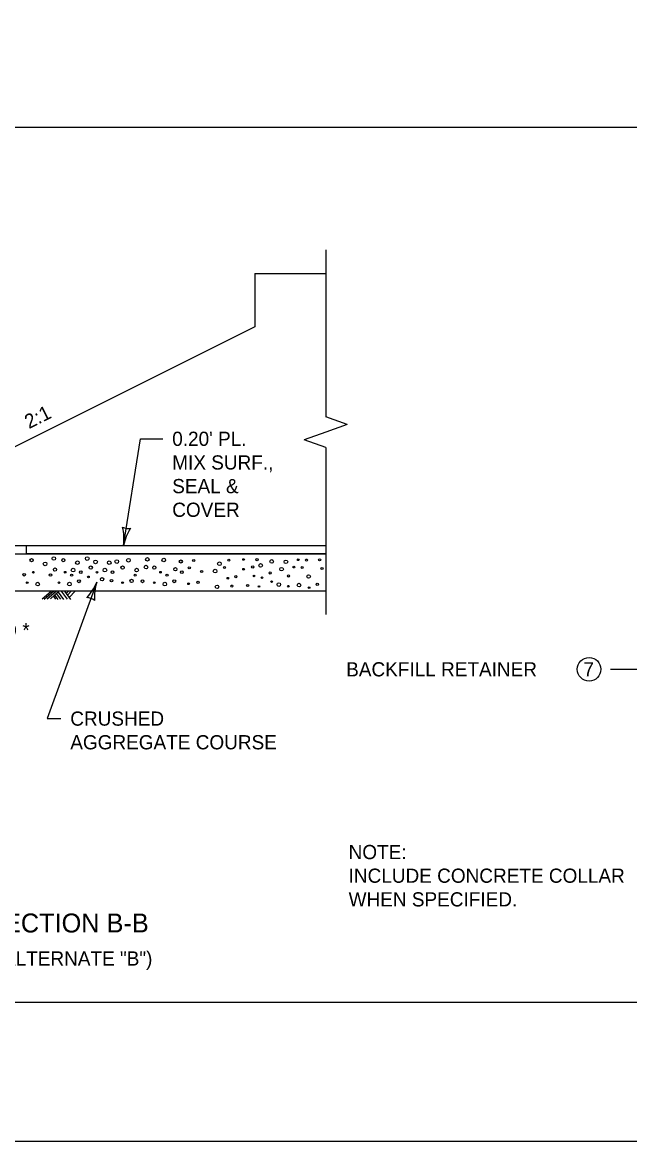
# Model space of a CAD drawing. Extents: x 49991.4 to 50021, y 49987.6 to 50011.4.
# Drawn here: x 50009.276 to 50011.844, y 49987.799 to 49992.53 of the extents above; entities that cross this region are included whole.
import ezdxf

# ---------------------------------------------------------------- set-up
doc = ezdxf.new("R2010")
doc.units = 0
for name, color, linetype in [('Level 1', 7, 'Continuous'), ('Level 2', 7, 'Continuous'), ('Level 3', 7, 'Continuous'), ('Level 6', 7, 'Continuous')]:
    doc.layers.add(name, color=color, linetype=linetype)

msp = doc.modelspace()

# ---------------------------------------------------------------- linework, layer by layer
at = {"layer": 'Level 1'}
for p, q in [((50010.2587, 49991.4692), (50010.2587, 49991.2434)), ((50010.2587, 49991.4692), (50010.5584, 49991.4692)), ((50010.2587, 49991.2434), (50008.4789, 49990.3535)), ((50008.5959, 49990.3188), (50010.5584, 49990.3188)), ((50009.2934, 49990.2833), (50009.2934, 49990.3188)), ((50009.2934, 49990.3188), (50010.5584, 49990.3188)), ((50010.5584, 49990.3188), (50010.5584, 49990.2833)), ((50008.5959, 49990.2833), (50010.5584, 49990.2833)), ((50010.5584, 49990.2833), (50009.2934, 49990.2833)), ((50008.4789, 49990.1273), (50010.5584, 49990.1273)), ((50009.3968, 49990.1248), (50009.3598, 49990.0925)), ((50009.4066, 49990.1248), (50009.3677, 49990.0908)), ((50009.4189, 49990.1249), (50009.3808, 49990.0918)), ((50009.4305, 49990.1252), (50009.3941, 49990.0934)), ((50009.4125, 49990.108), (50009.425, 49990.0908)), ((50009.4191, 49990.1152), (50009.4365, 49990.0914)), ((50009.4274, 49990.1218), (50009.4499, 49990.0909)), ((50009.4403, 49990.1255), (50009.4649, 49990.0919)), ((50009.4531, 49990.1257), (50009.4791, 49990.0901)), ((50009.4601, 49990.1143), (50009.4709, 49990.1257)), ((50009.4654, 49990.1074), (50009.4838, 49990.1268)), ((50009.4736, 49990.0982), (50009.499, 49990.1252)), ((50009.4072, 49990.1041), (50009.4156, 49990.0925))]:
    msp.add_line(p, q, dxfattribs=at)
for points in [[(49999.3835, 49998.9992), (50016.7501, 49998.9992), (50016.7501, 49987.7988), (49999.3835, 49987.7988)], [(49999.5517, 49992.0867), (50014.5753, 49992.0867), (50014.5753, 49988.387), (49999.5517, 49988.387)]]:
    msp.add_lwpolyline(points, close=True, dxfattribs=at)
for centre, radius in [((50009.3144, 49990.2567), 0.00684), ((50009.3719, 49990.2411), 0.00765), ((50009.4086, 49990.2637), 0.00765), ((50009.4488, 49990.2567), 0.00684), ((50009.5085, 49990.246), 0.00766), ((50009.5499, 49990.2636), 0.00765), ((50009.5852, 49990.2495), 0.00765), ((50009.643, 49990.246), 0.00766), ((50009.6747, 49990.2507), 0.00765), ((50009.7241, 49990.2564), 0.00765), ((50009.8042, 49990.2601), 0.00766), ((50009.8735, 49990.2572), 0.00765), ((50009.9458, 49990.251), 0.00684), ((50010.0001, 49990.2554), 0.0046), ((50010.1091, 49990.2416), 0.00766), ((50010.1487, 49990.2566), 0.0046), ((50010.211, 49990.2595), 0.00341), ((50010.2682, 49990.2591), 0.0046), ((50010.33, 49990.2514), 0.00766), ((50010.3901, 49990.2497), 0.00766), ((50010.4423, 49990.2584), 0.00341), ((50010.4775, 49990.257), 0.0046), ((50010.5327, 49990.2581), 0.0046), ((50009.322, 49990.2058), 0.00341), ((50009.4135, 49990.2171), 0.00684), ((50009.4565, 49990.2058), 0.00341), ((50009.4902, 49990.2149), 0.00766), ((50009.5223, 49990.2058), 0.00552), ((50009.5649, 49990.2256), 0.00684), ((50009.5909, 49990.2058), 0.00341), ((50009.6246, 49990.2149), 0.00766), ((50009.6568, 49990.2058), 0.00552), ((50009.6993, 49990.2256), 0.00684), ((50009.759, 49990.2149), 0.00766), ((50009.7987, 49990.2275), 0.00765), ((50009.8337, 49990.2256), 0.00684), ((50009.8598, 49990.2058), 0.00341), ((50009.9227, 49990.2185), 0.00684), ((50009.9499, 49990.2058), 0.00552), ((50009.9817, 49990.2243), 0.0046), ((50010.0338, 49990.2087), 0.0046), ((50010.0908, 49990.2105), 0.00766), ((50010.1303, 49990.2255), 0.0046), ((50010.211, 49990.2185), 0.00341), ((50010.2498, 49990.228), 0.0046), ((50010.2834, 49990.2345), 0.00766), ((50010.3237, 49990.2028), 0.0046), ((50010.3718, 49990.2186), 0.00766), ((50010.4239, 49990.2273), 0.00341), ((50010.4591, 49990.2259), 0.0046), ((50010.5431, 49990.2215), 0.0046), ((50009.2835, 49990.1952), 0.00552), ((50009.296, 49990.1615), 0.00341), ((50009.3404, 49990.1554), 0.00766), ((50009.3947, 49990.194), 0.00552), ((50009.4304, 49990.1615), 0.00341), ((50009.4748, 49990.1554), 0.00766), ((50009.484, 49990.1935), 0.0046), ((50009.5147, 49990.1676), 0.00613), ((50009.555, 49990.1861), 0.00341), ((50009.6129, 49990.1762), 0.00684), ((50009.6522, 49990.17), 0.00552), ((50009.6993, 49990.1615), 0.00341), ((50009.7374, 49990.1691), 0.00684), ((50009.7529, 49990.1935), 0.0046), ((50009.7835, 49990.1676), 0.00613), ((50009.8337, 49990.1615), 0.00341), ((50009.8782, 49990.1554), 0.00766), ((50009.8873, 49990.1935), 0.0046), ((50009.918, 49990.1676), 0.00613), ((50009.9785, 49990.1569), 0.00341), ((50010.0186, 49990.1627), 0.0046), ((50010.1445, 49990.1805), 0.00341), ((50010.1782, 49990.1871), 0.0046), ((50010.2282, 49990.1496), 0.0046), ((50010.2553, 49990.1898), 0.00341), ((50010.2893, 49990.1826), 0.00341), ((50010.3298, 49990.166), 0.00341), ((50010.3602, 49990.1537), 0.00766), ((50010.4012, 49990.1898), 0.0046), ((50010.4456, 49990.1515), 0.00766), ((50010.4863, 49990.1877), 0.00766), ((50010.5228, 49990.1545), 0.0046), ((50010.0988, 49990.1439), 0.00766), ((50010.1613, 49990.1471), 0.0046), ((50010.2762, 49990.1455), 0.00341), ((50010.4001, 49990.1466), 0.00341), ((50010.4884, 49990.1401), 0.00341)]:
    msp.add_circle(centre, radius, dxfattribs=at)
at = {"layer": 'Level 2'}
msp.add_circle((50011.6724, 49989.7954), 0.05, dxfattribs=at)
at = {"layer": 'Level 3'}
for p, q in [((50009.704, 49990.3188), (50009.7749, 49990.7698)), ((50009.7749, 49990.7698), (50009.8694, 49990.7698)), ((50009.5905, 49990.164), (50009.3808, 49989.587)), ((50011.7624, 49989.7954), (50012.0072, 49989.7954)), ((50009.3808, 49989.587), (50009.4382, 49989.587))]:
    msp.add_line(p, q, dxfattribs=at)
for centre, radius, start, end in [((50009.7239, 49990.4454), 0.0548, 243.2047, 278.927), ((50009.4723, 49990.3435), 0.233, 353.8932, 13.143), ((50009.922, 49990.2752), 0.2223, 148.5219, 168.7054), ((50009.3849, 49990.2484), 0.2223, 317.4833, 337.6668), ((50009.8131, 49990.0953), 0.233, 162.8546, 182.1044), ((50009.5467, 49990.0435), 0.0548, 52.1661, 87.8884)]:
    msp.add_arc(centre, radius, start, end, dxfattribs=at)
at = {"layer": 'Level 6'}
for p, q in [((50010.5584, 49991.5692), (50010.5584, 49990.863)), ((50010.6498, 49990.8306), (50010.5584, 49990.863)), ((50010.6498, 49990.8306), (50010.5584, 49990.7982)), ((50010.5584, 49990.7982), (50010.467, 49990.7658)), ((50010.5584, 49990.7334), (50010.467, 49990.7658)), ((50010.5584, 49990.7334), (50010.5584, 49990.0273))]:
    msp.add_line(p, q, dxfattribs=at)

# ---------------------------------------------------------------- texts
at = {"layer": 'Level 2'}
msp.add_text('2:1', height=0.06, rotation=26.5651, dxfattribs=at).set_placement((50009.3036, 49990.8105))
for s, height, p in [("0.20' PL.", 0.06, (50009.9094, 49990.7398)), ('MIX SURF.,', 0.06, (50009.9094, 49990.6398)), ('SEAL &', 0.06, (50009.9094, 49990.5398)), ('COVER', 0.06, (50009.9094, 49990.4398)), ('D *', 0.06, (50009.1951, 49989.9308)), ('BACKFILL RETAINER', 0.06, (50010.6451, 49989.7654)), ('7', 0.06, (50011.6486, 49989.7654)), ('CRUSHED', 0.06, (50009.4782, 49989.557)), ('AGGREGATE COURSE', 0.06, (50009.4782, 49989.457)), ('NOTE:', 0.06, (50010.6554, 49988.9929)), ('INCLUDE CONCRETE COLLAR', 0.06, (50010.6554, 49988.8929)), ('WHEN SPECIFIED.', 0.06, (50010.6554, 49988.7929)), ('SECTION B-B', 0.08, (50009.1265, 49988.6829)), ('(ALTERNATE "B")', 0.06, (50009.1668, 49988.543))]:
    msp.add_text(s, height=height, dxfattribs=at).set_placement(p)

doc.saveas('drawing.dxf')
